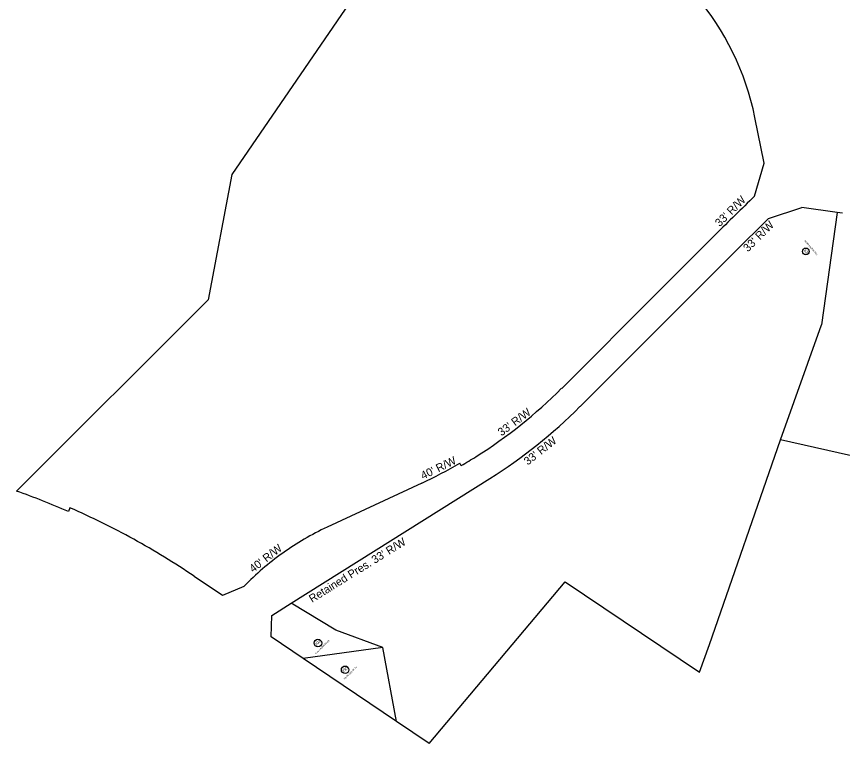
# Model space of a CAD drawing. Extents: x 1854757 to 1948870, y 823643 to 877716.
# Drawn here: x 1937602 to 1939703, y 831278 to 833128 of the extents above; entities that cross this region are included whole.
import ezdxf

# ---------------------------------------------------------------- set-up
doc = ezdxf.new("R2010")
doc.units = 0
for name, color, linetype in [('Butler baseline', 7, 'Continuous'), ('Flatiron trailer_2', 7, 'Continuous'), ('RD_EX_H2O_WetLd', 7, 'Continuous'), ('RD_SMD_Locator', 7, 'Continuous'), ('RD_SMD_Misc', 7, 'Continuous')]:
    doc.layers.add(name, color=color, linetype=linetype)

msp = doc.modelspace()

# ---------------------------------------------------------------- linework, layer by layer
at = {"layer": 'Butler baseline'}
for centre, radius in [((1939610, 832530.5), 8.44), ((1938368.7, 831533.7), 9.65), ((1938437.9, 831465.7), 9.65)]:
    msp.add_circle(centre, radius, dxfattribs=at)
at = {"layer": 'RD_EX_H2O_WetLd'}
for p, q in [((1938847.9, 833745.3), (1938149.2, 832726.3)), ((1938149.2, 832726.3), (1938089.2, 832407.5)), ((1939689.4, 832629.8), (1939649.7, 832343.3)), ((1937601.8, 831920.6), (1938089.2, 832407.5)), ((1939545.6, 832050.6), (1939649.7, 832343.3)), ((1939365.1, 831530), (1939545.6, 832050.6)), ((1939856.1, 831981.4), (1939545.6, 832050.6)), ((1937737.8, 831877.8), (1937733.7, 831868.5)), ((1938126.1, 831654.7), (1938054, 831703.6)), ((1938651.3, 831278.3), (1938997.5, 831690)), ((1938997.5, 831690), (1939339.7, 831459.4)), ((1938414.5, 831566.7), (1938300.5, 831635)), ((1938249.4, 831549.7), (1938251.1, 831604.2)), ((1938533.5, 831522.1), (1938414.5, 831566.7)), ((1938331, 831494.8), (1938249.4, 831549.7)), ((1939339.7, 831459.4), (1939365.1, 831530)), ((1938533.5, 831522.1), (1938331, 831494.8)), ((1938568.3, 831334.4), (1938533.5, 831522.1)), ((1938568.3, 831334.4), (1938331, 831494.8)), ((1938651.3, 831278.3), (1938568.3, 831334.4))]:
    msp.add_line(p, q, dxfattribs=at)
for centre, radius, start, end in [((1936953.1, 830084.5), 1947.4, 66.37, 70.5435), ((1936952.4, 830076.7), 1964.9, 61.1715, 66.4402), ((1936951.5, 830077.2), 1964.9, 55.868, 61.1411)]:
    msp.add_arc(centre, radius, start, end, dxfattribs=at)
at = {"layer": 'RD_SMD_Misc'}
for p, q in [((1939503.9, 832754.9), (1939480.5, 832871.6)), ((1939479.7, 832670.9), (1939503.9, 832754.9)), ((1939514.9, 832613.8), (1939600.2, 832642)), ((1939689.4, 832629.8), (1939600.2, 832642)), ((1939703.2, 832627.9), (1939689.4, 832629.8)), ((1939514.9, 832613.8), (1939427.4, 832527.3)), ((1939237.3, 832431.3), (1939380.7, 832574)), ((1939427.4, 832527.3), (1939035.4, 832135.4)), ((1938988.8, 832182), (1939237.3, 832431.3)), ((1938733.1, 831985.2), (1938729.6, 831991.4)), ((1938300.5, 831635), (1938806.3, 831952.7)), ((1938632.8, 831940.9), (1938391.8, 831828.6)), ((1938180.3, 831677.8), (1938126.1, 831654.7)), ((1938251.1, 831604.2), (1938300.5, 831635))]:
    msp.add_line(p, q, dxfattribs=at)
for centre, radius, start, end in [((1938803.6, 832733), 691, 11.5651, 40.591), ((1947468.8, 824409.9), 11492.2, 134.04135, 134.73198), ((1938111.2, 833058.5), 1240.2, 302.1555, 315.035), ((1938111.8, 833059.1), 1306.2, 302.1191, 314.9974), ((1938108.6, 833056.8), 1240.2, 300.2324, 302.3009), ((1938111.3, 833058.5), 1233.2, 295.0175, 300.088), ((1938693.7, 831181.5), 714.1, 115.0062, 125.4932), ((1938693.8, 831181.6), 714.1, 125.5042, 135.9809)]:
    msp.add_arc(centre, radius, start, end, dxfattribs=at)

# ---------------------------------------------------------------- texts
at = {"layer": 'Butler baseline'}
for s, rotation, p in [('24', 130.5238, (1939616.9, 832528.2)), ('292', 44.9725, (1938364.7, 831525.8)), ('293', 44.9725, (1938433.9, 831457.7))]:
    msp.add_text(s, height=7.5, rotation=rotation, dxfattribs=at).set_placement(p)
at = {"layer": 'Flatiron trailer_2'}
for s, rotation, p in [('TMS R03300-06-09', 130.5238, (1939640.8, 832522.6)), ('TMS R03300-06-08', 45.6993, (1938364.1, 831504.6)), ('TMS R03300-06-10', 45.6993, (1938433.9, 831437.2))]:
    msp.add_text(s, height=4, rotation=rotation, dxfattribs=at).set_placement(p)
at = {"layer": 'RD_SMD_Locator'}
for s, height, rotation, p in [("33' R/W", 20.37, 44.9229, (1939390.8, 832591.8)), ("33' R/W", 20.37, 44.9229, (1939462.6, 832527.9)), ("33' R/W", 20.37, 36.8251, (1938835.6, 832059.4)), ("33' R/W", 20.37, 38.1906, (1938902.5, 831985.4)), ("40' R/W", 20.37, 26.1525, (1938636.3, 831949.3)), ("Retained Pres. 33' R/W", 20.368, 31.9173, (1938353.7, 831635.8)), ("40' R/W", 20.37, 37.987, (1938203.9, 831712.1))]:
    msp.add_text(s, height=height, rotation=rotation, dxfattribs=at).set_placement(p)

doc.saveas('drawing.dxf')
